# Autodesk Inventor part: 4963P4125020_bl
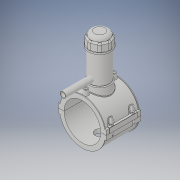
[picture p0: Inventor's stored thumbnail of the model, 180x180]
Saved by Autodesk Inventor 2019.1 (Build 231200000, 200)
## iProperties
Created: 2017-07
Part Number: 4963P4125020_bl
Material: Generic
Document SubType Name: Modeling
Designer: KIM
Density: 1 g/cm^3
Appearance: Default
Author: KIM
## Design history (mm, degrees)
derived "4963P4.ipt"
feature "Solid1::4963P4.ipt" dims "ScaleForDerivedMember" = 10
feature "Solid2::4963P4.ipt" dims "ScaleForDerivedMember" = 10
feature "Solid3::4963P4.ipt" dims "ScaleForDerivedMember" = 10
tag "TaggingFeature1"
body "Solid1"
body "Solid2"
body "Solid3"
other parameters: "d0" = 125 [user parameter], "d2" = 162 [user parameter], "d3" = 31.25 [user parameter], "d4" = 118 [user parameter], "d5" = 0 [user parameter], "d6" = 0.1 [user parameter], "d8" = 0 [user parameter], "d19" = 6 [user parameter], "d20" = 6 [user parameter], "d21" = 70.8 [user parameter], "d23" = 0 [user parameter], "d24" = 35.4 [user parameter], "d26" = 0 [user parameter], "d27" = 3 [user parameter], "d28" = 3 [user parameter], "d29" = 3 [user parameter], "d30" = 41.66667 [user parameter], "d31" = 6 [user parameter], "d32" = 0 [user parameter], "d33" = 0 [user parameter], "d34" = 0.6 [user parameter], "d40" = 79.3 [user parameter], "d41" = 75 [user parameter], "d43" = 0 [user parameter], "d45" = 0 [user parameter], "d47" = 147.05 [user parameter], "d70" = 15 [user parameter], "d72" = 0 [user parameter], "d73" = 6 [user parameter], "d75" = 5 [user parameter], "d76" = 0 [user parameter], "d77" = 6.25 [user parameter], "d78" = 92.5 [user parameter], "d79" = 15 [user parameter], "d80" = 47.2 [user parameter], "d82" = 5 deg [user parameter], "d84" = 4 [user parameter], "d85" = 14 [user parameter], "d86" = 0 [user parameter], "d87" = 3 [user parameter], "d88" = 0 [user parameter], "d89" = 1 [user parameter], "d90" = 1 [user parameter], "d91" = 94.4 [user parameter], "d92" = 0 [user parameter], "d93" = 0.5 [user parameter], "d94" = 65.78947 [user parameter], "d96" = 155.55 [user parameter], "d97" = 2.36 [user parameter], "d98" = 0 [user parameter], "d102" = 1.25 [user parameter], "d120" = 140 deg [user parameter], "d121" = 24.228 [user parameter], "d122" = 20 deg [user parameter], "d123" = 305 [user parameter], "d124" = 91.5 [user parameter], "d126" = 0 [user parameter], "d143" = 128.75 [user parameter], "d145" = 21.15385 [user parameter], "d149" = 1.875 [user parameter], "d150" = 23.26923 [user parameter], "d153" = 118 [user parameter], "d154" = 0 [user parameter], "d156" = 76.25 [user parameter], "d157" = 160 deg [user parameter], "d159" = 5.5 [user parameter], "d161" = 1.875 [user parameter], "d162" = 70.8 [user parameter], "d163" = 0 [user parameter], "d164" = 62.5 [user parameter], "d167" = 12.5 [user parameter], "d168" = 74.39024 [user parameter], "d170" = 3.75 [user parameter], "d172" = 0 [user parameter], "d173" = 1 [user parameter], "d175" = 62.5 [user parameter], "d176" = 20 deg [user parameter], "d177" = 8.75 [user parameter], "d178" = 27.5 [user parameter], "d180" = 0 [user parameter], "d183" = 11 [user parameter], "d184" = 7 [user parameter], "d185" = 38.35 [user parameter], "d186" = 38.35 [user parameter], "d187" = 76.25 [user parameter], "d188" = 8.25 [user parameter], "d189" = 8.75 [user parameter], "d190" = 0 [user parameter], "d191" = 114.375 [user parameter], "d193" = 8 [user parameter], "d194" = 4.13 [user parameter], "d195" = 90 deg [user parameter], "d197" = 0 [user parameter], "d199" = 0 [user parameter], "d200" = 13.75 [user parameter], "d202" = 0 [user parameter], "d203" = 177 [user parameter], "d204" = 71.25 [user parameter], "d205" = 52.5 [user parameter], "d206" = 63.75 [user parameter], "d207" = 132.75 [user parameter], "d208" = 138.06 [user parameter], "d209" = 164.61 [user parameter], "d210" = 64.5 [user parameter], "d211" = 75 [user parameter], "d213" = 36 [user parameter], "d216" = 0 [user parameter], "d217" = 12.5 [user parameter], "d218" = 12.5 [user parameter], "d219" = 2.5 [user parameter], "d222" = 125 [user parameter], "d224" = 0 [user parameter], "d227" = 16 [user parameter], "d228" = 125 [user parameter], "d230" = 5 [user parameter], "d_" = 125 [user parameter], "B_" = 162 [user parameter], "L_" = 118 [user parameter], "d_t" = 6 [user parameter], "H_2" = 177 [user parameter]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
